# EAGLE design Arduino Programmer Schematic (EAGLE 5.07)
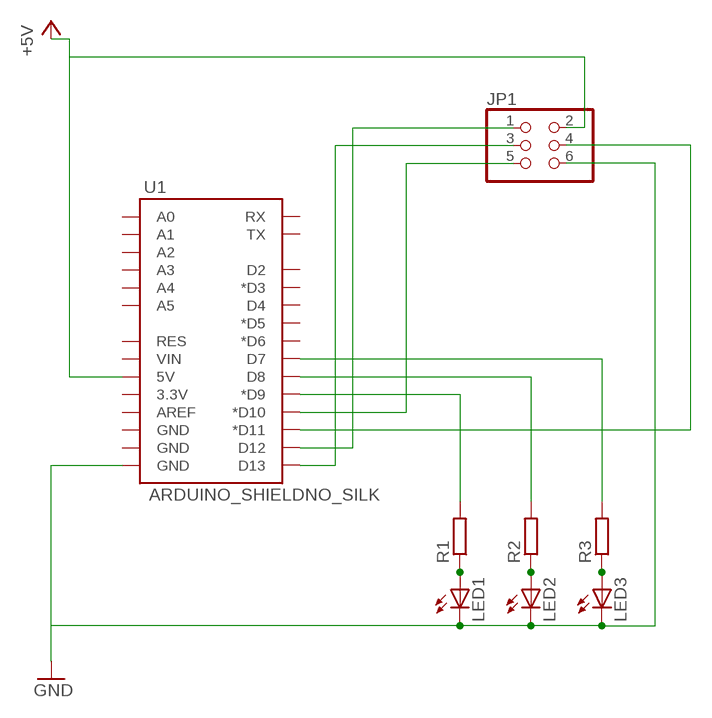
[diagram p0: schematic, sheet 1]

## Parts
JP1  PINHD-2X3  [2X03]
LED1  LED5MM  [LED5MM]
LED2  LED5MM  [LED5MM]
LED3  LED5MM  [LED5MM]
R1  R-EU_0207/7  [0207/7]
R2  R-EU_0207/7  [0207/7]
R3  R-EU_0207/7  [0207/7]
U1  ARDUINO_SHIELDNO_SILK  [DUEMILANOVE_VIAS]

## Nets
+5V: JP1.2 U1.5V
GND: JP1.6 LED1.K(C) LED2.K(C) LED3.K(C) U1.GND@0(GND)
N$1: LED1.A R1.1
N$2: LED2.A R2.1
N$3: LED3.A R3.1
N$4: R1.2 U1.D9(*D9)
N$5: R2.2 U1.D8
N$6: R3.2 U1.D7
N$7: JP1.3 U1.D13
N$8: JP1.1 U1.D12
N$9: JP1.4 U1.D11(*D11)
N$10: JP1.5 U1.D10(*D10)
Unconnected: U1.3.3V U1.A0 U1.A1 U1.A2 U1.A3 U1.A4 U1.A5 U1.AREF U1.D2 U1.D3(*D3) U1.D4 U1.D5(*D5) U1.D6(*D6) U1.GND@1(GND) U1.GND@2(GND) U1.RES U1.RX U1.TX U1.VIN

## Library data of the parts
JP1 = pinhead:PINHD-2X3: PIN HEADER
LED1-LED3 = led:LED: LED
R1-R3 = resistor:R-EU_: RESISTOR, European symbol
U1 = SparkFun:ARDUINO_SHIELD

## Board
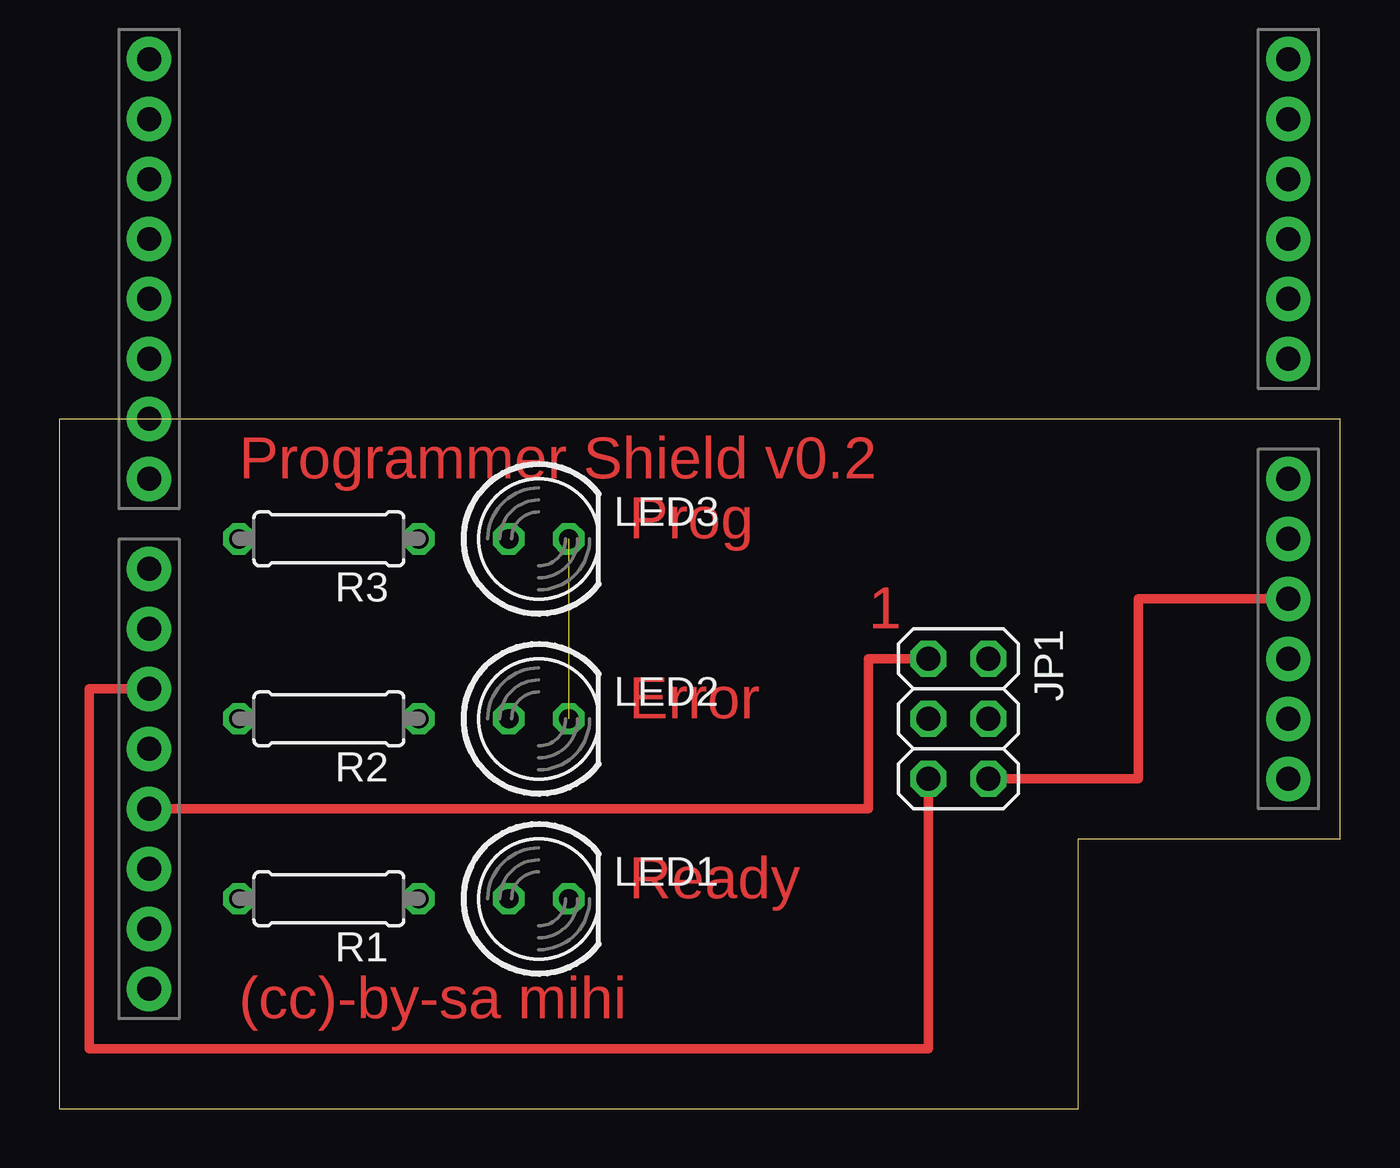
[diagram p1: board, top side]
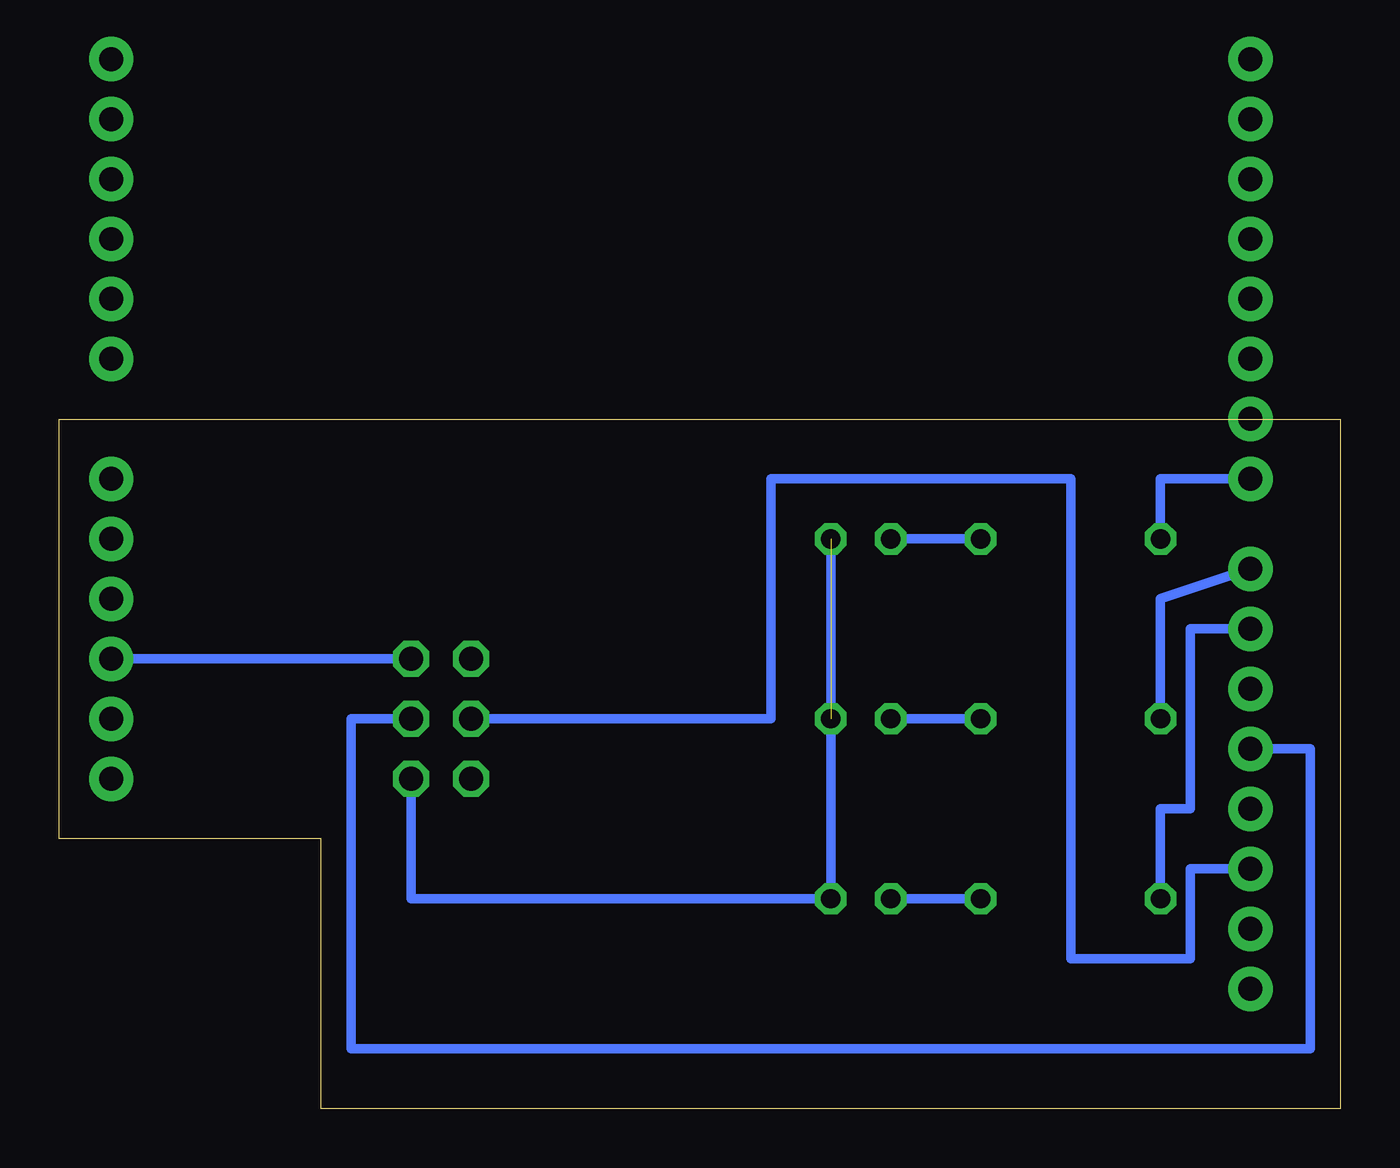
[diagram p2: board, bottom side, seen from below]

Size 54.28 x 29.2 mm. Coordinates in mm from the lower left corner, seen from the top.
Outline: 0,0 43.18,0 43.18,11.43 54.28,11.43 54.28,29.2 0,29.2 0,0
Copper layers (1*16): Top 0.035mm / dielectric 1.5mm / Bottom 0.035mm
Design rules "default": minimum track width 10mil, minimum drill 24mil, track to track 8mil, track to pad 8mil, pad to pad 8mil, via to via 8mil, smd to smd 8mil, copper to edge 40mil, drill to drill 8mil, minimum pad ring 10mil, minimum via ring 8mil, stop-mask expansion 4mil, vias tented up to drill 0mil, thermal gap 10mil

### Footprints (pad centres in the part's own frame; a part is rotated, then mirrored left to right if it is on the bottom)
2X03 = drill 1.016 octagon: 1 -2.54,-1.27; 2 -2.54,1.27; 3 0,-1.27; 4 0,1.27; 5 2.54,-1.27; 6 2.54,1.27
LED5MM = drill 0.813 octagon: A -1.27,0; K 1.27,0
0207/7 = drill 0.813 octagon: 1 -3.81,0; 2 3.81,0
DUEMILANOVE_VIAS = drill 1.016 pad 1.88 round: 3.3V 50.8,13.97; 5V 50.8,16.51; A0 50.8,29.21; A1 50.8,31.75; A2 50.8,34.29; A3 50.8,36.83; A4 50.8,39.37; A5 50.8,41.91; AREF 2.54,2.54; D2 2.54,36.83; D3 2.54,34.29; D4 2.54,31.75; D5 2.54,29.21; D6 2.54,26.67; D7 2.54,24.13; D8 2.54,20.32; D9 2.54,17.78; D10 2.54,15.24; D11 2.54,12.7; D12 2.54,10.16; D13 2.54,7.62; GND@0 50.8,19.05; GND@1 50.8,21.59; GND@2 2.54,5.08; RES 50.8,11.43; RX 2.54,41.91; TX 2.54,39.37; VIN 50.8,24.13

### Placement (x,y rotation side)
JP1  38.1,16.51 270 top
LED1  20.32,8.89 0 top
LED2  20.32,16.51 0 top
LED3  20.32,24.13 0 top
R1  11.43,8.89 180 top
R2  11.43,16.51 180 top
R3  11.43,24.13 180 top
U1  1.27,2.54 0 top

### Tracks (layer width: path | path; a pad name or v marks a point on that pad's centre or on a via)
+5V
  Bottom 0.406: U1.5V JP1.2
GND  (1 unrouted)
  Top 0.406: U1.GND@0 45.72,21.59 45.72,13.97 JP1.6
  Bottom 0.406: LED3.K LED1.K 39.37,8.89 JP1.6
N$1
  Bottom 0.406: LED1.A R1.1
N$2
  Bottom 0.406: LED2.A R2.1
N$3
  Bottom 0.406: R3.1 LED3.A
N$4
  Bottom 0.406: U1.D9 6.35,20.32 6.35,12.7 7.62,12.7 R1.2
N$5
  Bottom 0.406: U1.D8 7.62,21.59 R2.2
N$6
  Bottom 0.406: R3.2 7.62,26.67 U1.D7
N$7
  Bottom 0.406: U1.D13 6.35,10.16 6.35,6.35 11.43,6.35 11.43,26.67 24.13,26.67 24.13,16.51 JP1.3
N$8
  Top 0.406: U1.D12 34.29,12.7 34.29,19.05 JP1.1
N$9
  Bottom 0.406: JP1.4 41.91,16.51 41.91,2.54 1.27,2.54 1.27,15.24 U1.D11
N$10
  Top 0.406: U1.D10 1.27,17.78 1.27,2.54 36.83,2.54 JP1.5

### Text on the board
Top: Programmer Shield v0.2 | Prog | 1 | Error | Ready | (cc)-by-sa mihi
